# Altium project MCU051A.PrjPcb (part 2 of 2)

## Sheet MCU051A_EVM_Hardware.SchDoc
size 431 x 279 mm; Date: Not shown in title block; ApprovedBy: Not shown in title block; CheckedBy: Not shown in title block; Author: Not shown in title block; CompanyName: Not shown in title block; Engineer: Not shown in title block; Organization: Not shown in title block; Address1: Not shown in title block; Address2: Not shown in title block; Address3: Not shown in title block; Address4: Not shown in title block; DocumentNumber: 1; Revision: Use project parameter SCH_Rev; SheetNumber: 4; SheetTotal: 4; PageSetup: Record=PageOptions¦CenterHorizontal=True¦CenterVertical=True¦PrintScale=1.00¦XCorrection=1.00¦YCorrection=1.00¦PrintKind=0¦BorderSize=5000000¦LeftOffset=0¦BottomOffset=0¦Orientation=2¦PaperLength=1000¦PaperWidth=1000¦Scale=100¦PaperSource=15¦PrintQuality=600¦MediaType=1¦DitherType=10¦PaperKind=Letter¦PrintScaleMode=1
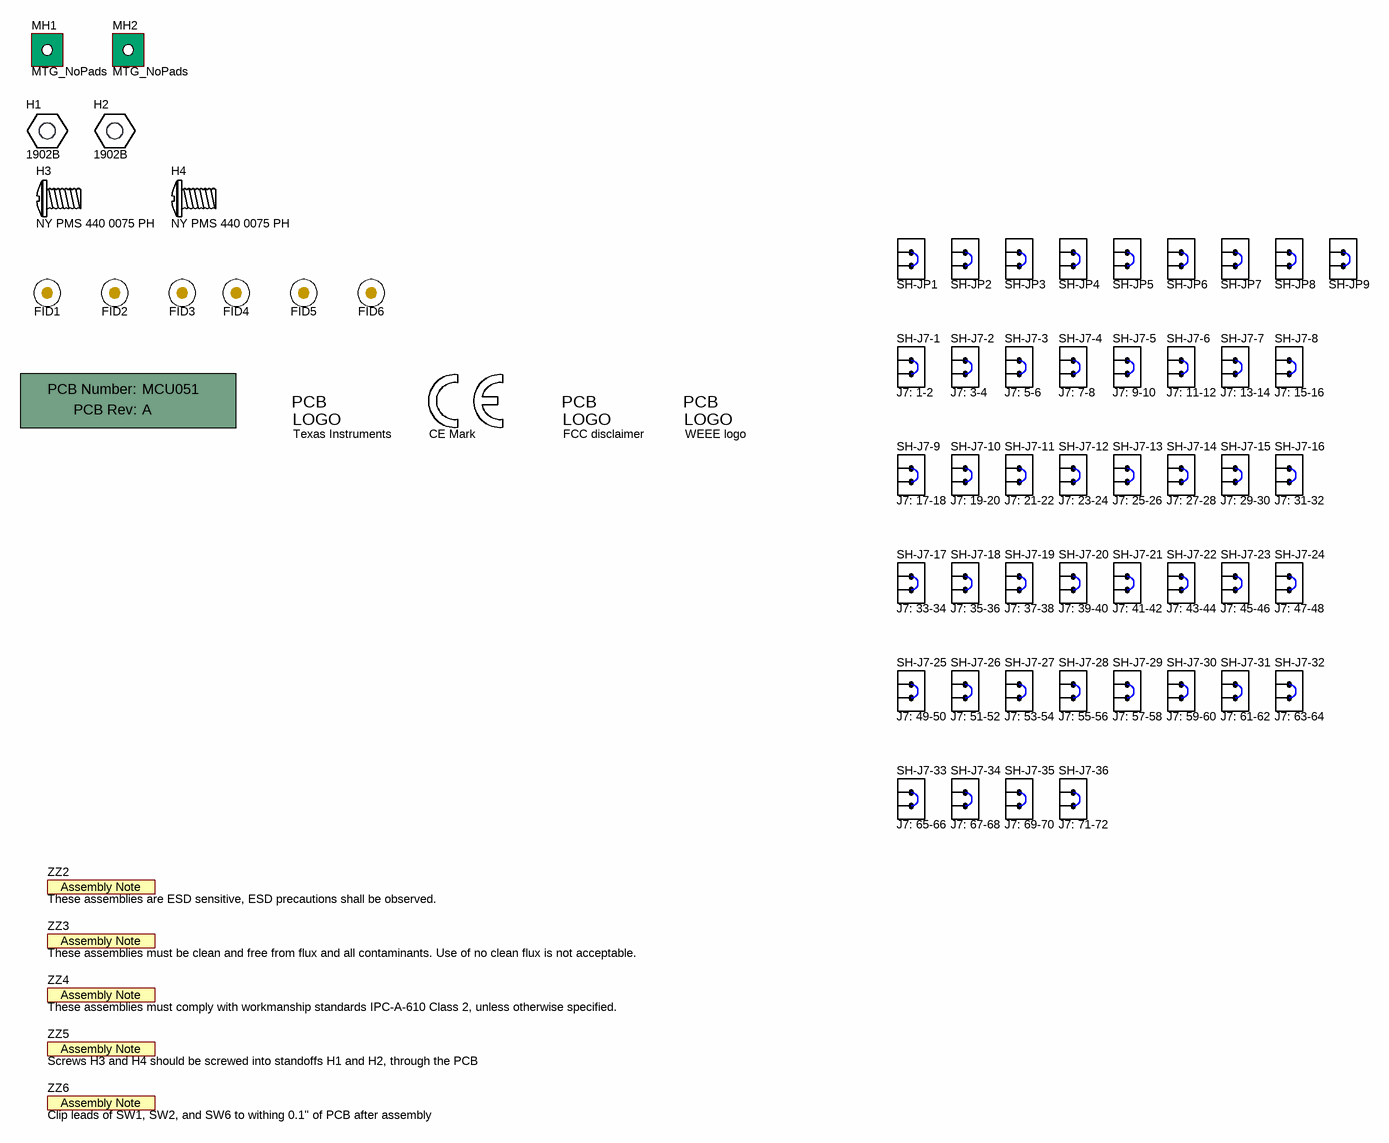
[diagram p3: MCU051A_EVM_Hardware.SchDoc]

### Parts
!PCB  Printed Circuit Board  (value not drawn)  (mechanical)
FID1  Fiducial  [Fiducial10-20]  (value not drawn)
FID2  Fiducial  [Fiducial10-20]  (value not drawn)
FID3  Fiducial  [Fiducial10-20]  (value not drawn)
FID4  Fiducial  [Fiducial10-20]  (value not drawn)
FID5  Fiducial  [Fiducial10-20]  (value not drawn)
FID6  Fiducial  [Fiducial10-20]  (value not drawn)
H1  1902B  [Keystone_1902B]
H2  1902B  [Keystone_1902B]
H3  NY PMS 440 0075 PH  (mechanical)
H4  NY PMS 440 0075 PH  (mechanical)
Logo1  Texas Instruments  [TI_Stacked_Overlay_Small]  (no BOM)
Logo2  CE Mark  [CE_Mark_5mm]  (no BOM)
Logo3  FCC disclaimer  [FCC_disclaimer]  (no BOM)
Logo4  WEEE logo  [WEEE_Minimum]  (no BOM)
MH1  MTG_NoPads  [NPTH125mil]  (no BOM)
MH2  MTG_NoPads  [NPTH125mil]  (no BOM)
SH-J7-1  Note: J7: 1-2  [SNT-100-BK-G]  (hidden comment: SNT-100-BK-G)
SH-J7-2  Note: J7: 3-4  [SNT-100-BK-G]  (hidden comment: SNT-100-BK-G)
SH-J7-3  Note: J7: 5-6  [SNT-100-BK-G]  (hidden comment: SNT-100-BK-G)
SH-J7-4  Note: J7: 7-8  [SNT-100-BK-G]  (hidden comment: SNT-100-BK-G)
SH-J7-5  Note: J7: 9-10  [SNT-100-BK-G]  (hidden comment: SNT-100-BK-G)
SH-J7-6  Note: J7: 11-12  [SNT-100-BK-G]  (hidden comment: SNT-100-BK-G)
SH-J7-7  Note: J7: 13-14  [SNT-100-BK-G]  (hidden comment: SNT-100-BK-G)
SH-J7-8  Note: J7: 15-16  [SNT-100-BK-G]  (hidden comment: SNT-100-BK-G)
SH-J7-9  Note: J7: 17-18  [SNT-100-BK-G]  (hidden comment: SNT-100-BK-G)
SH-J7-10  Note: J7: 19-20  [SNT-100-BK-G]  (hidden comment: SNT-100-BK-G)
SH-J7-11  Note: J7: 21-22  [SNT-100-BK-G]  (hidden comment: SNT-100-BK-G)
SH-J7-12  Note: J7: 23-24  [SNT-100-BK-G]  (hidden comment: SNT-100-BK-G)
SH-J7-13  Note: J7: 25-26  [SNT-100-BK-G]  (hidden comment: SNT-100-BK-G)
SH-J7-14  Note: J7: 27-28  [SNT-100-BK-G]  (hidden comment: SNT-100-BK-G)
SH-J7-15  Note: J7: 29-30  [SNT-100-BK-G]  (hidden comment: SNT-100-BK-G)
SH-J7-16  Note: J7: 31-32  [SNT-100-BK-G]  (hidden comment: SNT-100-BK-G)
SH-J7-17  Note: J7: 33-34  [SNT-100-BK-G]  (hidden comment: SNT-100-BK-G)
SH-J7-18  Note: J7: 35-36  [SNT-100-BK-G]  (hidden comment: SNT-100-BK-G)
SH-J7-19  Note: J7: 37-38  [SNT-100-BK-G]  (hidden comment: SNT-100-BK-G)
SH-J7-20  Note: J7: 39-40  [SNT-100-BK-G]  (hidden comment: SNT-100-BK-G)
SH-J7-21  Note: J7: 41-42  [SNT-100-BK-G]  (hidden comment: SNT-100-BK-G)
SH-J7-22  Note: J7: 43-44  [SNT-100-BK-G]  (hidden comment: SNT-100-BK-G)
SH-J7-23  Note: J7: 45-46  [SNT-100-BK-G]  (hidden comment: SNT-100-BK-G)
SH-J7-24  Note: J7: 47-48  [SNT-100-BK-G]  (hidden comment: SNT-100-BK-G)
SH-J7-25  Note: J7: 49-50  [SNT-100-BK-G]  (hidden comment: SNT-100-BK-G)
SH-J7-26  Note: J7: 51-52  [SNT-100-BK-G]  (hidden comment: SNT-100-BK-G)
SH-J7-27  Note: J7: 53-54  [SNT-100-BK-G]  (hidden comment: SNT-100-BK-G)
SH-J7-28  Note: J7: 55-56  [SNT-100-BK-G]  (hidden comment: SNT-100-BK-G)
SH-J7-29  Note: J7: 57-58  [SNT-100-BK-G]  (hidden comment: SNT-100-BK-G)
SH-J7-30  Note: J7: 59-60  [SNT-100-BK-G]  (hidden comment: SNT-100-BK-G)
SH-J7-31  Note: J7: 61-62  [SNT-100-BK-G]  (hidden comment: SNT-100-BK-G)
SH-J7-32  Note: J7: 63-64  [SNT-100-BK-G]  (hidden comment: SNT-100-BK-G)
SH-J7-33  Note: J7: 65-66  [SNT-100-BK-G]  (hidden comment: SNT-100-BK-G)
SH-J7-34  Note: J7: 67-68  [SNT-100-BK-G]  (hidden comment: SNT-100-BK-G)
SH-J7-35  Note: J7: 69-70  [SNT-100-BK-G]  (hidden comment: SNT-100-BK-G)
SH-J7-36  Note: J7: 71-72  [SNT-100-BK-G]  (hidden comment: SNT-100-BK-G)
SH-JP1  SNT-100-BK-G  [SNT-100-BK-G]  (value not drawn)
SH-JP2  SNT-100-BK-G  [SNT-100-BK-G]  (value not drawn)
SH-JP3  SNT-100-BK-G  [SNT-100-BK-G]  (value not drawn)
SH-JP4  SNT-100-BK-G  [SNT-100-BK-G]  (value not drawn)
SH-JP5  SNT-100-BK-G  [SNT-100-BK-G]  (value not drawn)
SH-JP6  SNT-100-BK-G  [SNT-100-BK-G]  (value not drawn)
SH-JP7  SNT-100-BK-G  [SNT-100-BK-G]  (value not drawn)
SH-JP8  SNT-100-BK-G  [SNT-100-BK-G]  (value not drawn)
SH-JP9  SNT-100-BK-G  [SNT-100-BK-G]  (value not drawn)
ZZ2  These assemblies are ESD sensitive, ESD precautions shall be observed.  [AssemblyNote]  (no BOM)
ZZ3  These assemblies must be clean and free from flux and all contaminants. Use of no clean flux is not acceptable.  [AssemblyNote]  (no BOM)
ZZ4  These assemblies must comply with workmanship standards IPC-A-610 Class 2, unless otherwise specified.  [AssemblyNote]  (no BOM)
ZZ5  Screws H3 and H4 should be screwed into standoffs H1 and H2, through the PCB  [AssemblyNote]  (no BOM)
ZZ6  Clip leads of SW1, SW2, and SW6 to withing 0.1" of PCB after assembly  [AssemblyNote]  (no BOM)

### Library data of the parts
!PCB = CMP-0003618-2: Manufacturer: Any; PartNumber: MCU051
FID1-FID6 = CMP-0077181-1: Fiducial mark.  There is nothing to buy or mount.
H1 H2 = CMP-0003658-1: Manufacturer: Keystone; CompType: Hardware
H3 H4 = CMP-0077235-1: MACHINE SCREW PAN PHILLIPS 4-40; Manufacturer: B&F Fastener Supply; CompType: Standoff
Logo1 = CMP-0074838-1: Texas Instrument Corporate Signature; SymbolCreator: a0412235; Lib Reference: TI_Logo; Library Reference: Logo
Logo2 = CMP-0074844-1: SymbolCreator: a0412235
Logo3 = CMP-0074847-1: FCC_disclaimer; Library Reference: Logo
Logo4 = CMP-0074769-1
MH1 MH2 = CMP-0078424-2: PCB Mounting Hole, No Pad; Manufacturer: Any; Key: Mounting Hole (non-standard) No Pad
SH-J7-1-SH-J7-36 SH-JP1-SH-JP9 = CMP-0003623-1: Shunt, 100mil, Gold plated, Black; Alternate PartNumber: 969102-0000-DA; Manufacturer: Samtec; Alternate Manufacturer: 3M; Value: 1x2
ZZ2 = CMP-0077236-1
ZZ3 = CMP-0077237-1
ZZ4-ZZ6 = CMP-0077238-1

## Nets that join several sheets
5V0: MCU051A_Power_JTAG (6 pins), MCU051A_MSP432E_Device (C28.1 U3.5), MCU051A_LCD_Memory (J1/J3.21 J9.2 J9.34)
AVSS: MCU051A_Power_JTAG (R43.2), MCU051A_MSP432E_Device (C29.1 C30.1 J6.7 U1.G4)
VDD: MCU051A_Power_JTAG (JP2.2 SW6.2 SW6.4), MCU051A_MSP432E_Device (43 pins), MCU051A_LCD_Memory (J1/J3.1 J9.1 J9.33 JP9.1)
VDDA: MCU051A_Power_JTAG (JP3.2), MCU051A_MSP432E_Device (C29.2 C30.2 J6.6 U1.F3)
VSS: MCU051A_Power_JTAG (R42.2), MCU051A_MSP432E_Device (78 pins), MCU051A_LCD_Memory (16 pins)
PA0: MCU051A_Power_JTAG (SW4.3), MCU051A_MSP432E_Device (J5.32 U1.V3)
PA1: MCU051A_Power_JTAG (SW4.1), MCU051A_MSP432E_Device (J5.33 U1.W3)
PA2: MCU051A_Power_JTAG (SW3.5), MCU051A_MSP432E_Device (U1.T6), MCU051A_LCD_Memory (J2/J4.40)
PA3: MCU051A_Power_JTAG (SW3.7), MCU051A_MSP432E_Device (U1.U5), MCU051A_LCD_Memory (J2/J4.39)
PA4: MCU051A_Power_JTAG (SW3.1), MCU051A_MSP432E_Device (U1.V4), MCU051A_LCD_Memory (J2/J4.38)
PA5: MCU051A_Power_JTAG (SW3.3), MCU051A_MSP432E_Device (U1.W4), MCU051A_LCD_Memory (J2/J4.37)
PA6: MCU051A_MSP432E_Device (U1.V5), MCU051A_LCD_Memory (J7.55)
PA7: MCU051A_MSP432E_Device (U1.R7), MCU051A_LCD_Memory (J7.53)
PB2: MCU051A_Power_JTAG (R11.1 SW5.3), MCU051A_MSP432E_Device (U1.A17), MCU051A_LCD_Memory (J7.17)
PB3: MCU051A_Power_JTAG (R10.1 SW5.1), MCU051A_MSP432E_Device (U1.B17), MCU051A_LCD_Memory (J7.15)
PB4: MCU051A_MSP432E_Device (U1.C6), MCU051A_LCD_Memory (J9.31)
PB5: MCU051A_MSP432E_Device (U1.B6), MCU051A_LCD_Memory (J1/J3.24)
PB6: MCU051A_MSP432E_Device (U1.F2), MCU051A_LCD_Memory (J1/J3.9)
PB7: MCU051A_MSP432E_Device (U1.F1), MCU051A_LCD_Memory (J1/J3.10)
PC0: MCU051A_Power_JTAG (R17.2 R20.1 R36.2 R38.2), MCU051A_MSP432E_Device (J5.26 U1.B15)
PC1: MCU051A_Power_JTAG (R18.2 R21.1 R34.2 R35.2), MCU051A_MSP432E_Device (J5.12 U1.C15)
PC2: MCU051A_Power_JTAG (R19.2 R22.1 R41.2), MCU051A_MSP432E_Device (J5.15 U1.D14)
PC3: MCU051A_Power_JTAG (JA.13 JB.6 R37.2 R40.2), MCU051A_MSP432E_Device (J5.13 U1.C14)
PC4: MCU051A_MSP432E_Device (U1.M2), MCU051A_LCD_Memory (J7.57)
PC5: MCU051A_MSP432E_Device (U1.M1), MCU051A_LCD_Memory (J7.59)
PC6: MCU051A_MSP432E_Device (U1.L2), MCU051A_LCD_Memory (J7.61)
PC7: MCU051A_MSP432E_Device (U1.K3), MCU051A_LCD_Memory (J7.63)
PD0: MCU051A_MSP432E_Device (U1.C2), MCU051A_LCD_Memory (J2/J4.14)
PD1: MCU051A_MSP432E_Device (U1.C1), MCU051A_LCD_Memory (J2/J4.15)
PD2: MCU051A_MSP432E_Device (U1.D2), MCU051A_LCD_Memory (J2/J4.12)
PD3: MCU051A_MSP432E_Device (U1.D1), MCU051A_LCD_Memory (J1/J3.7)
PD4: MCU051A_MSP432E_Device (U1.A4), MCU051A_LCD_Memory (J2/J4.36)
PD5: MCU051A_MSP432E_Device (U1.B4), MCU051A_LCD_Memory (J2/J4.35)
PE0: MCU051A_MSP432E_Device (U1.H3), MCU051A_LCD_Memory (J1/J3.28)
PE1: MCU051A_MSP432E_Device (U1.H2), MCU051A_LCD_Memory (J1/J3.2)
PE2: MCU051A_MSP432E_Device (U1.G1), MCU051A_LCD_Memory (J2/J4.32)
PE3: MCU051A_MSP432E_Device (U1.G2), MCU051A_LCD_Memory (J2/J4.31)
PE4: MCU051A_MSP432E_Device (U1.A5), MCU051A_LCD_Memory (J1/J3.6)
PE5: MCU051A_MSP432E_Device (U1.B5), MCU051A_LCD_Memory (J1/J3.23)
PE6: MCU051A_MSP432E_Device (U1.A7), MCU051A_LCD_Memory (J9.37)
PE7: MCU051A_MSP432E_Device (U1.B7), MCU051A_LCD_Memory (J9.38)
PF0: MCU051A_Power_JTAG (J12.18), MCU051A_MSP432E_Device (J5.28 U1.U6)
PF1: MCU051A_Power_JTAG (J12.16), MCU051A_MSP432E_Device (J5.27 U1.V6)
PF2: MCU051A_Power_JTAG (J12.14), MCU051A_MSP432E_Device (J5.29 U1.W6)
PF3: MCU051A_Power_JTAG (J12.12), MCU051A_MSP432E_Device (J5.31 U1.T7)
PF4: MCU051A_Power_JTAG (J12.20), MCU051A_MSP432E_Device (J5.30 U1.V7)
PF6: MCU051A_MSP432E_Device (U1.T8), MCU051A_LCD_Memory (J9.4)
PF7: MCU051A_MSP432E_Device (U1.U8), MCU051A_LCD_Memory (J9.11)
PG0: MCU051A_MSP432E_Device (U1.N15), MCU051A_LCD_Memory (J7.49)
PG1: MCU051A_MSP432E_Device (U1.T14), MCU051A_LCD_Memory (J7.51)
PH0: MCU051A_MSP432E_Device (U1.P4), MCU051A_LCD_Memory (J7.71)
PH1: MCU051A_MSP432E_Device (U1.R2), MCU051A_LCD_Memory (J7.69)
PH2: MCU051A_MSP432E_Device (U1.R1), MCU051A_LCD_Memory (J7.67)
PH4: MCU051A_MSP432E_Device (U1.R3), MCU051A_LCD_Memory (J1/J3.5)
PH5: MCU051A_MSP432E_Device (U1.T2), MCU051A_LCD_Memory (J1/J3.29)
PH6: MCU051A_MSP432E_Device (U1.U2), MCU051A_LCD_Memory (J1/J3.30)
PH7: MCU051A_MSP432E_Device (U1.V2), MCU051A_LCD_Memory (J2/J4.17)
PJ2: MCU051A_MSP432E_Device (U1.H17), MCU051A_LCD_Memory (J9.23)
PJ3: MCU051A_MSP432E_Device (U1.F16), MCU051A_LCD_Memory (J9.24)
PJ4: MCU051A_MSP432E_Device (U1.F18), MCU051A_LCD_Memory (J9.25)
PJ5: MCU051A_MSP432E_Device (U1.E17), MCU051A_LCD_Memory (J9.26)
PJ6: MCU051A_MSP432E_Device (U1.N1), MCU051A_LCD_Memory (J9.8)
PJ7: MCU051A_MSP432E_Device (U1.K5), MCU051A_LCD_Memory (J2/J4.34)
PK0: MCU051A_MSP432E_Device (U1.J1), MCU051A_LCD_Memory (J1/J3.25)
PK1: MCU051A_MSP432E_Device (U1.J2), MCU051A_LCD_Memory (J1/J3.26)
PK2: MCU051A_MSP432E_Device (U1.K1), MCU051A_LCD_Memory (J1/J3.27)
PK3: MCU051A_MSP432E_Device (U1.K2), MCU051A_LCD_Memory (J7.65)
PK4: MCU051A_MSP432E_Device (U1.U19), MCU051A_LCD_Memory (J7.7)
PK5: MCU051A_MSP432E_Device (U1.V17), MCU051A_LCD_Memory (J7.9)
PK6: MCU051A_MSP432E_Device (U1.V16), MCU051A_LCD_Memory (J7.21)
PK7: MCU051A_MSP432E_Device (U1.W16), MCU051A_LCD_Memory (J7.23)
PL0: MCU051A_MSP432E_Device (U1.G16), MCU051A_LCD_Memory (J7.39)
PL1: MCU051A_MSP432E_Device (U1.H19), MCU051A_LCD_Memory (J7.37)
PL2: MCU051A_MSP432E_Device (U1.G18), MCU051A_LCD_Memory (J7.35)
PL3: MCU051A_MSP432E_Device (U1.J18), MCU051A_LCD_Memory (J7.33)
PL4: MCU051A_MSP432E_Device (U1.H18), MCU051A_LCD_Memory (J7.19)
PL5: MCU051A_MSP432E_Device (U1.G19), MCU051A_LCD_Memory (J7.5)
PM0: MCU051A_MSP432E_Device (U1.K18), MCU051A_LCD_Memory (J7.41)
PM1: MCU051A_MSP432E_Device (U1.K19), MCU051A_LCD_Memory (J7.43)
PM2: MCU051A_MSP432E_Device (U1.L18), MCU051A_LCD_Memory (J7.45)
PM3: MCU051A_MSP432E_Device (U1.L19), MCU051A_LCD_Memory (J7.47)
PM4: MCU051A_MSP432E_Device (U1.M18), MCU051A_LCD_Memory (J2/J4.33)
PM6: MCU051A_MSP432E_Device (U1.N19), MCU051A_LCD_Memory (J2/J4.11)
PM7: MCU051A_MSP432E_Device (U1.N18), MCU051A_LCD_Memory (J2/J4.19)
PN3: MCU051A_MSP432E_Device (U1.B10), MCU051A_LCD_Memory (J7.11)
PN4: MCU051A_MSP432E_Device (U1.A10), MCU051A_LCD_Memory (J7.3)
PN5: MCU051A_MSP432E_Device (U1.B9), MCU051A_LCD_Memory (J7.1)
PN6: MCU051A_MSP432E_Device (U1.T12), MCU051A_LCD_Memory (J9.22)
PN7: MCU051A_MSP432E_Device (U1.U12), MCU051A_LCD_Memory (J9.21)
PP0: MCU051A_MSP432E_Device (U1.D6), MCU051A_LCD_Memory (J1/J3.3)
PP1: MCU051A_MSP432E_Device (U1.D7), MCU051A_LCD_Memory (J1/J3.4)
PP2: MCU051A_MSP432E_Device (U1.B13), MCU051A_LCD_Memory (J7.13)
PP3: MCU051A_MSP432E_Device (U1.C12), MCU051A_LCD_Memory (J2/J4.13)
PP4: MCU051A_MSP432E_Device (U1.D8), MCU051A_LCD_Memory (J1/J3.8)
PP5: MCU051A_MSP432E_Device (U1.B12), MCU051A_LCD_Memory (J2/J4.18)
PP6: MCU051A_MSP432E_Device (U1.B8), MCU051A_LCD_Memory (J9.36)
PP7: MCU051A_MSP432E_Device (U1.A8), MCU051A_LCD_Memory (J9.35)
PQ0: MCU051A_MSP432E_Device (U1.E3), MCU051A_LCD_Memory (J7.31)
PQ1: MCU051A_MSP432E_Device (U1.E2), MCU051A_LCD_Memory (J7.29)
PQ2: MCU051A_MSP432E_Device (U1.H4), MCU051A_LCD_Memory (J7.27)
PQ3: MCU051A_MSP432E_Device (U1.M4), MCU051A_LCD_Memory (J7.25)
PR0: MCU051A_MSP432E_Device (U1.N5), MCU051A_LCD_Memory (J9.5)
PR1: MCU051A_MSP432E_Device (U1.N4), MCU051A_LCD_Memory (J9.3)
PR2: MCU051A_MSP432E_Device (U1.N2), MCU051A_LCD_Memory (J9.6)
PR3: MCU051A_MSP432E_Device (U1.V8), MCU051A_LCD_Memory (J9.12)
PR4: MCU051A_MSP432E_Device (U1.P3), MCU051A_LCD_Memory (J9.9)
PR5: MCU051A_MSP432E_Device (U1.P2), MCU051A_LCD_Memory (J9.10)
PR6: MCU051A_MSP432E_Device (U1.W9), MCU051A_LCD_Memory (J9.13)
PR7: MCU051A_MSP432E_Device (U1.R10), MCU051A_LCD_Memory (J9.14)
PS0: MCU051A_MSP432E_Device (U1.D12), MCU051A_LCD_Memory (J9.29)
PS1: MCU051A_MSP432E_Device (U1.D13), MCU051A_LCD_Memory (J9.30)
PS3: MCU051A_MSP432E_Device (U1.A14), MCU051A_LCD_Memory (J9.32)
PS4: MCU051A_MSP432E_Device (U1.V9), MCU051A_LCD_Memory (J9.15)
PS5: MCU051A_MSP432E_Device (U1.T13), MCU051A_LCD_Memory (J9.16)
PS6: MCU051A_MSP432E_Device (U1.U10), MCU051A_LCD_Memory (J9.17)
PS7: MCU051A_MSP432E_Device (U1.R13), MCU051A_LCD_Memory (J9.18)
PT0: MCU051A_MSP432E_Device (U1.W10), MCU051A_LCD_Memory (J9.19)
PT1: MCU051A_MSP432E_Device (U1.V10), MCU051A_LCD_Memory (J9.20)
PT2: MCU051A_MSP432E_Device (U1.E18), MCU051A_LCD_Memory (J9.27)
PT3: MCU051A_MSP432E_Device (U1.F17), MCU051A_LCD_Memory (J9.28)
RSTn: MCU051A_Power_JTAG (BSL.4 J12.10 JA.15 JB.10), MCU051A_MSP432E_Device (R3.1 R4.1 SW1.1 U1.P18), MCU051A_LCD_Memory (J2/J4.16)

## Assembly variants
001: not fitted FID1 FID2 FID3 FID4 FID5 FID6 MH1 MH2 R1 R7 R26 R28 TP1 TP2 TP3 TP4 TP5 TP6 TP7 TP8 TP9 TP10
